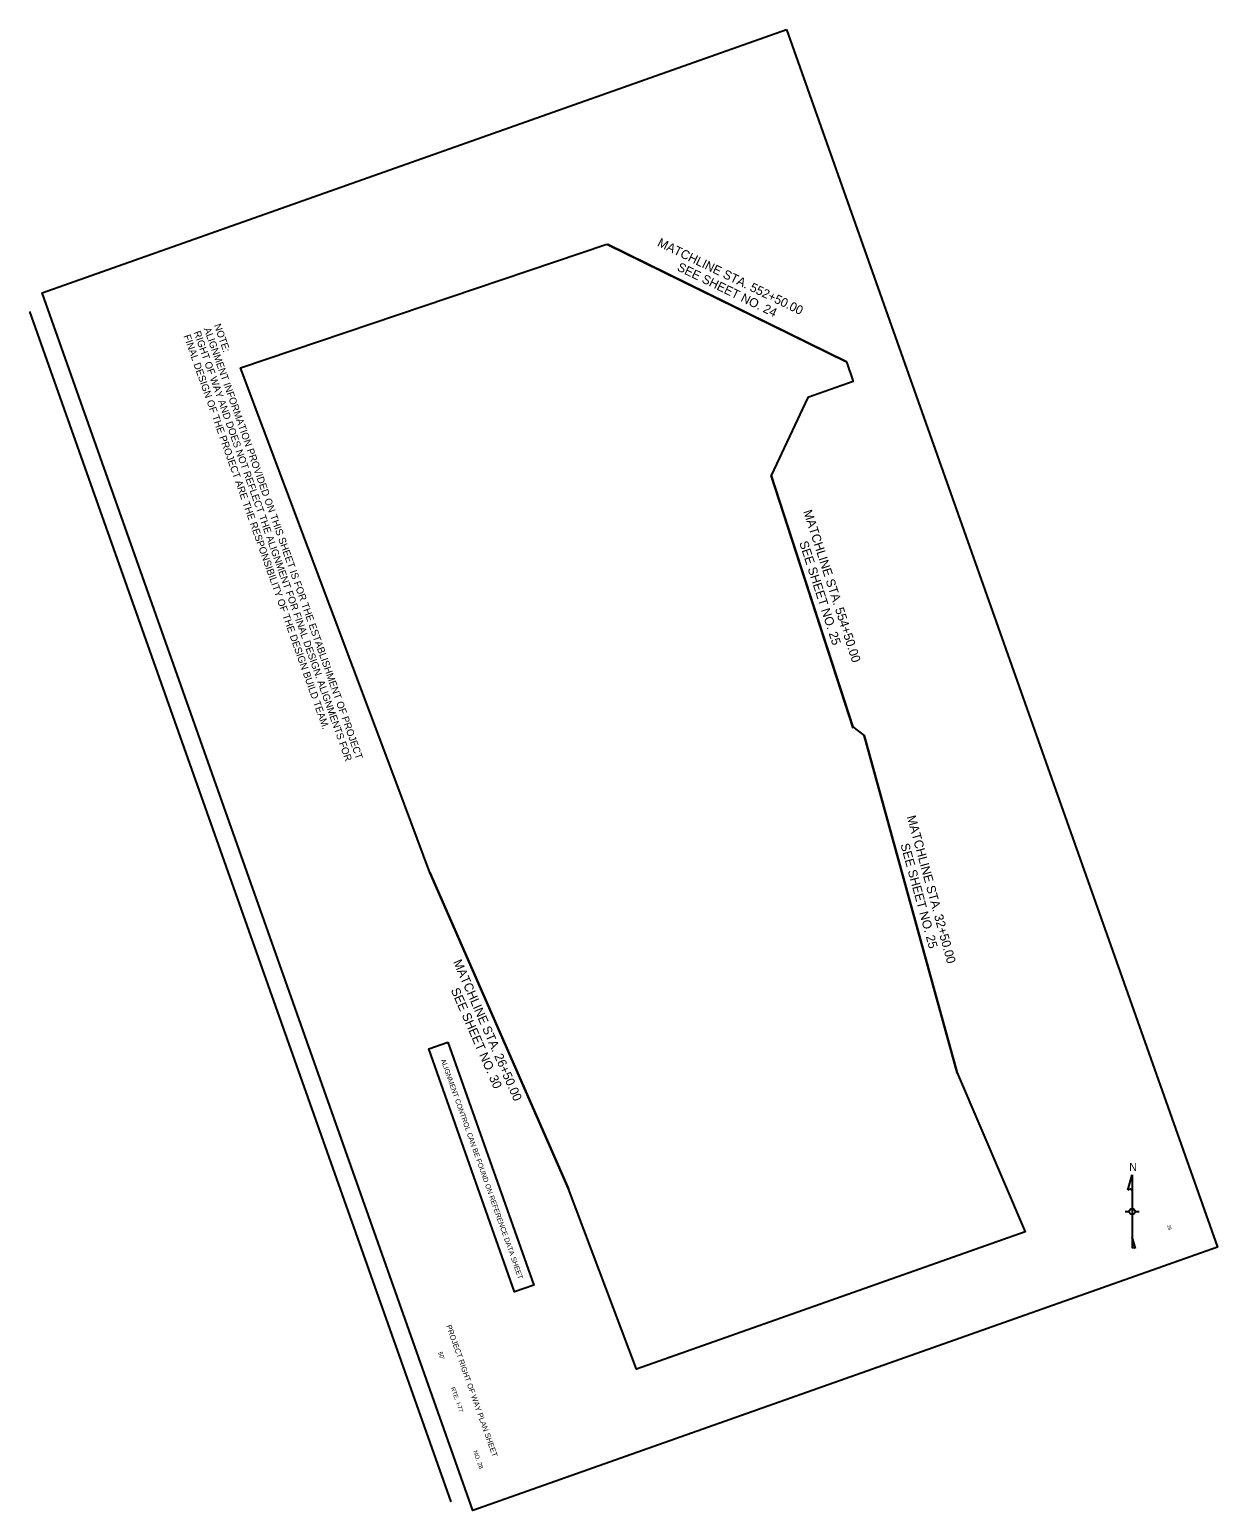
# Model space of a CAD drawing. Extents: x 2004383 to 2006037, y 1136152 to 1138216.
import ezdxf

# ---------------------------------------------------------------- set-up
doc = ezdxf.new("R2010")
doc.units = 0
for name, color, linetype in [('North Arrow', 7, 'Continuous'), ('RD_SHT_IplotShp', 7, 'Continuous'), ('RD_SHT_MatchLine', 7, 'Continuous'), ('RD_SHT_Misc1', 7, 'Continuous'), ('RD_SHT_ShtClip', 7, 'Continuous'), ('RD_SHT_TX', 7, 'Continuous')]:
    doc.layers.add(name, color=color, linetype=linetype)

msp = doc.modelspace()

# ---------------------------------------------------------------- linework, layer by layer
at = {"layer": 'North Arrow'}
for p, q in [((2005912.8, 1136598.4), (2005918.8, 1136619.4)), ((2005918.8, 1136619.4), (2005918.8, 1136597.2)), ((2005918.8, 1136619.4), (2005918.8, 1136517.2)), ((2005909, 1136568.3), (2005914.7, 1136568.3)), ((2005922.8, 1136568.3), (2005928.5, 1136568.3)), ((2005918.8, 1136533), (2005918.8, 1136517.2)), ((2005923.3, 1136516.9), (2005918.8, 1136533))]:
    msp.add_line(p, q, dxfattribs=at)
msp.add_circle((2005918.8, 1136568.3), 4.02, dxfattribs=at)
for centre, radius, start, end in [((2005915.4, 1136595.9), 3.59, 22.3707, 136.1387), ((2005920.9, 1136514.7), 3.3, 43.3397, 130.5607)]:
    msp.add_arc(centre, radius, start, end, dxfattribs=at)
at = {"layer": 'RD_SHT_IplotShp'}
msp.add_lwpolyline([(2005437.1, 1138215.7), (2006037.5, 1136518.7), (2005000.4, 1136151.9), (2004400.1, 1137848.8)], close=True, dxfattribs=at)
at = {"layer": 'RD_SHT_MatchLine'}
for p, q in [((2005520.6, 1137752.8), (2005188.2, 1137916)), ((2005530, 1137242), (2005415.7, 1137594.3)), ((2005675, 1136761.7), (2005545.6, 1137231.7)), ((2004940.5, 1137040.7), (2005133.6, 1136600.2))]:
    msp.add_line(p, q, dxfattribs=at)
at = {"layer": 'RD_SHT_ShtClip'}
msp.add_lwpolyline([(2005187.1, 1137916.5), (2005520.6, 1137752.8), (2005530.3, 1137725.3), (2005466.7, 1137702.8), (2005415.7, 1137594.3), (2005529.5, 1137243.8), (2005545.6, 1137231.7), (2005675, 1136761.7), (2005769.8, 1136540.1), (2005228.3, 1136348.6), (2005133.6, 1136600.2), (2004940.5, 1137040.7), (2004896, 1137159.3), (2004676.4, 1137744.4)], close=True, dxfattribs=at)
at = {"layer": 'RD_SHT_TX'}
msp.add_line((2004382.8, 1137822.9), (2004969.7, 1136163.7), dxfattribs=at)
msp.add_line((2004382.8, 1137822.9), (2004969.7, 1136163.7), dxfattribs=at)
msp.add_lwpolyline([(2004965.4, 1136804.4), (2005085.2, 1136465.8), (2005058.4, 1136456.4), (2004938.7, 1136795)], close=True, dxfattribs=at)

# ---------------------------------------------------------------- texts
at = {"layer": 'North Arrow'}
msp.add_text('N', height=11.1, dxfattribs=at).set_placement((2005914.7, 1136624.9))
at = {"layer": 'RD_SHT_MatchLine'}
for s, rotation, p in [('MATCHLINE STA. 552+50.00', 334.1631, (2005256.3, 1137914.6)), ('SEE SHEET NO. 24', 334.1631, (2005283.8, 1137880.5)), ('MATCHLINE STA. 554+50.00', 287.9765, (2005460.4, 1137544.1)), ('SEE SHEET NO. 25', 287.9765, (2005454.8, 1137500.6)), ('MATCHLINE STA. 32+50.00', 285.3889, (2005604.7, 1137118.6)), ('SEE SHEET NO. 25', 285.3889, (2005595.9, 1137079.8)), ('MATCHLINE STA. 26+50.00', 293.5949, (2004972.5, 1136916.4)), ('SEE SHEET NO. 30', 293.5949, (2004969.3, 1136877))]:
    msp.add_text(s, height=12.5, rotation=rotation, dxfattribs=at).set_placement(p)
at = {"layer": 'RD_SHT_Misc1'}
for s, p in [('ALIGNMENT INFORMATION PROVIDED ON THIS SHEET IS FOR THE ESTABLISHMENT OF PROJECT', (2004625.3, 1137798.7)), ('NOTE:', (2004639.4, 1137803.7)), ('FINAL DESIGN OF THE PROJECT ARE THE RESPONSIBILITY OF THE DESIGN BUILD TEAM.', (2004597, 1137788.7)), ('RIGHT OF WAY AND DOES NOT REFLECT THE ALIGNMENT FOR FINAL DESIGN. ALIGNMENTS FOR', (2004611.1, 1137793.7))]:
    msp.add_text(s, height=10, rotation=289.482, dxfattribs=at).set_placement(p)
at = {"layer": 'RD_SHT_TX'}
for s, height, p in [('ALIGNMENT CONTROL CAN BE FOUND ON REFERENCE DATA SHEET', 7, (2004955.4, 1136779.8)), ('28', 4.5, (2005967.4, 1136548.8)), ('PROJECT RIGHT OF WAY PLAN SHEET', 7.5, (2004963, 1136409)), ("50'", 6, (2004951.8, 1136371.8)), ('RTE.', 6, (2004969.2, 1136322.7)), ('I-77', 6, (2004976.8, 1136301.2)), ('NO.', 6, (2005000.5, 1136234.2)), ('28', 6, (2005006.3, 1136217.9))]:
    msp.add_text(s, height=height, rotation=289.482, dxfattribs=at).set_placement(p)

doc.saveas('drawing.dxf')
